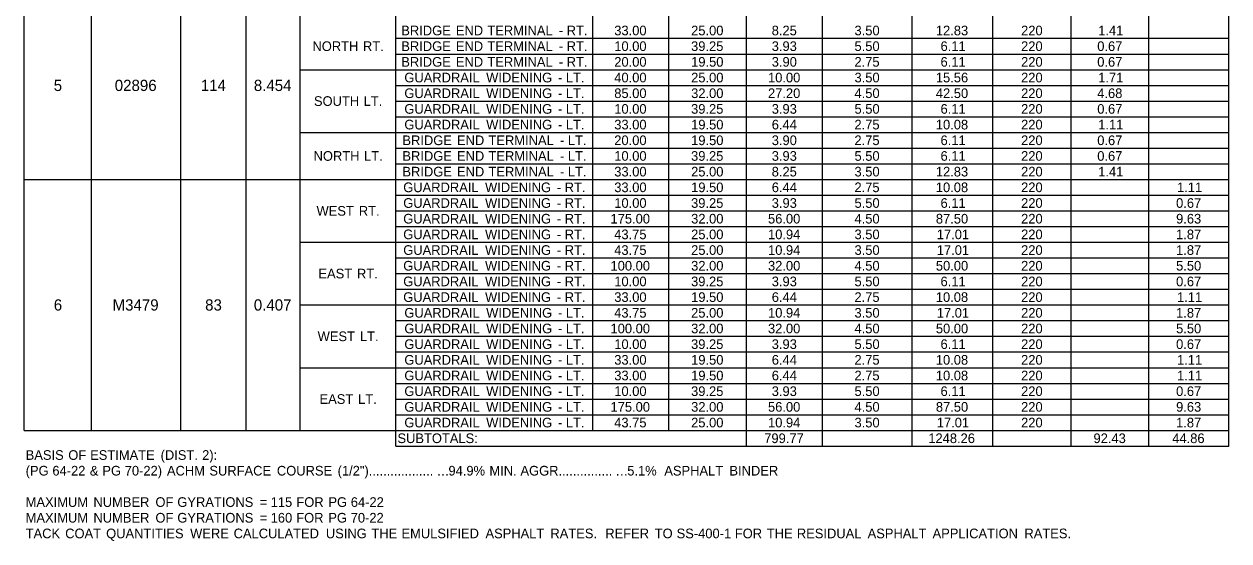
# Model space of a CAD drawing. Extents: x 542596 to 1930787, y -1948294 to 596640.
# Drawn here: x 552220 to 552968, y -1946907 to -1946586 of the extents above; entities that cross this region are included whole.
import ezdxf

# ---------------------------------------------------------------- set-up
doc = ezdxf.new("R2010")
doc.units = 0
doc.layers.add('Default', color=7, linetype='Continuous')

msp = doc.modelspace()

# ---------------------------------------------------------------- linework, layer by layer
at = {"layer": 'Default'}
for p, q in [((552219.67, -1946838.51), (552219.67, -1946129.69)), ((552261.6, -1946838.51), (552261.6, -1946129.69)), ((552317.17, -1946838.51), (552317.17, -1946129.69)), ((552357.64, -1946838.51), (552357.64, -1946129.69)), ((552391.27, -1946838.51), (552391.27, -1946129.69)), ((552450.75, -1946848.26), (552450.75, -1946129.69)), ((552573.11, -1946838.51), (552573.11, -1946129.69)), ((552620.4, -1946838.51), (552620.4, -1946129.69)), ((552715.95, -1946848.26), (552715.95, -1946129.69)), ((552968.47, -1946848.26), (552968.47, -1946129.69)), ((552668.66, -1946848.26), (552668.66, -1946155.04)), ((552771.52, -1946848.26), (552771.52, -1946155.04)), ((552821.74, -1946848.26), (552821.74, -1946155.04)), ((552870.49, -1946848.26), (552870.49, -1946155.04)), ((552918.75, -1946848.26), (552918.75, -1946155.04)), ((552821.74, -1946672.76), (552821.74, -1946565.51)), ((552450.75, -1946594.76), (552968.47, -1946594.76)), ((552620.4, -1946604.51), (552620.4, -1946594.76)), ((552668.66, -1946838.51), (552668.66, -1946594.76)), ((552771.52, -1946848.26), (552771.52, -1946594.76)), ((552450.75, -1946604.51), (552968.47, -1946604.51)), ((552391.27, -1946614.26), (552450.75, -1946614.26)), ((552391.27, -1946614.26), (552450.75, -1946614.26)), ((552450.75, -1946614.26), (552918.75, -1946614.26)), ((552573.11, -1946653.26), (552573.11, -1946614.26)), ((552620.4, -1946838.51), (552620.4, -1946614.26)), ((552821.74, -1946614.26), (552870.49, -1946614.26)), ((552870.49, -1946614.26), (552968.47, -1946614.26)), ((552450.75, -1946624.01), (552968.47, -1946624.01)), ((552450.75, -1946633.76), (552968.47, -1946633.76)), ((552450.75, -1946643.51), (552968.47, -1946643.51)), ((552391.27, -1946653.26), (552968.47, -1946653.26)), ((552391.27, -1946653.26), (552450.75, -1946653.26)), ((552450.75, -1946663.01), (552968.47, -1946663.01)), ((552450.75, -1946672.76), (552968.47, -1946672.76)), ((552219.67, -1946682.51), (552450.75, -1946682.51)), ((552219.67, -1946682.51), (552620.4, -1946682.51)), ((552450.75, -1946682.51), (552668.66, -1946682.51)), ((552573.11, -1946838.51), (552573.11, -1946682.51)), ((552620.4, -1946682.51), (552771.52, -1946682.51)), ((552715.95, -1946682.51), (552771.52, -1946682.51)), ((552771.52, -1946682.51), (552968.47, -1946682.51)), ((552821.74, -1946682.51), (552870.49, -1946682.51)), ((552821.74, -1946838.51), (552821.74, -1946682.51)), ((552870.49, -1946682.51), (552918.75, -1946682.51)), ((552918.75, -1946682.51), (552968.47, -1946682.51)), ((552450.75, -1946692.26), (552968.47, -1946692.26)), ((552450.75, -1946702.01), (552968.47, -1946702.01)), ((552450.75, -1946711.76), (552968.47, -1946711.76)), ((552391.27, -1946721.51), (552968.47, -1946721.51)), ((552391.27, -1946721.51), (552450.75, -1946721.51)), ((552450.75, -1946731.26), (552968.47, -1946731.26)), ((552450.75, -1946741.01), (552968.47, -1946741.01)), ((552450.75, -1946750.76), (552968.47, -1946750.76)), ((552391.27, -1946760.51), (552968.47, -1946760.51)), ((552391.27, -1946760.51), (552450.75, -1946760.51)), ((552450.75, -1946770.26), (552968.47, -1946770.26)), ((552450.75, -1946780.01), (552968.47, -1946780.01)), ((552450.75, -1946789.76), (552968.47, -1946789.76)), ((552391.27, -1946799.51), (552715.95, -1946799.51)), ((552391.27, -1946799.51), (552450.75, -1946799.51)), ((552668.66, -1946799.51), (552715.95, -1946799.51)), ((552715.95, -1946799.51), (552968.47, -1946799.51)), ((552450.75, -1946809.26), (552968.47, -1946809.26)), ((552450.75, -1946819.01), (552715.95, -1946819.01)), ((552668.66, -1946819.01), (552715.95, -1946819.01)), ((552715.95, -1946819.01), (552968.47, -1946819.01)), ((552450.75, -1946828.76), (552715.95, -1946828.76)), ((552668.66, -1946828.76), (552715.95, -1946828.76)), ((552715.95, -1946828.76), (552968.47, -1946828.76)), ((552219.67, -1946838.51), (552968.47, -1946838.51)), ((552391.27, -1946838.51), (552450.75, -1946838.51)), ((552450.75, -1946838.51), (552771.52, -1946838.51)), ((552450.75, -1946848.26), (552450.75, -1946838.51)), ((552771.52, -1946838.51), (552821.74, -1946838.51)), ((552821.74, -1946838.51), (552968.47, -1946838.51)), ((552870.49, -1946848.26), (552870.49, -1946838.51)), ((552450.75, -1946848.26), (552968.47, -1946848.26))]:
    msp.add_line(p, q, dxfattribs=at)

# ---------------------------------------------------------------- texts
for s, height, p in [('BRIDGE', 6, (552454.1, -1946592.89)), (' END', 6, (552485.8, -1946592.89)), (' TERMINAL', 6, (552505.38, -1946592.89)), (' RT.', 6, (552554.66, -1946592.89)), ('33.00', 6, (552586.47, -1946592.89)), ('25.00', 6, (552634.25, -1946592.89)), ('8.25', 6, (552684.32, -1946592.89)), ('3.50', 6, (552735.78, -1946592.89)), ('12.83', 6, (552786.34, -1946592.89)), ('220', 6, (552839.32, -1946592.89)), ('1.41', 6, (552887.24, -1946592.89)), (' -', 6, (552549.8, -1946592.89)), ('NORTH', 6, (552398.9, -1946602.64)), (' RT.', 6, (552428.03, -1946602.64)), ('BRIDGE', 6, (552454.1, -1946602.64)), (' END', 6, (552485.8, -1946602.64)), (' TERMINAL', 6, (552505.38, -1946602.64)), (' -', 6, (552549.8, -1946602.64)), (' RT.', 6, (552554.66, -1946602.64)), ('10.00', 6, (552586.47, -1946602.64)), ('39.25', 6, (552634.21, -1946602.64)), ('3.93', 6, (552684.34, -1946602.64)), ('5.50', 6, (552735.78, -1946602.64)), ('6.11', 6, (552789.25, -1946602.64)), ('220', 6, (552839.32, -1946602.64)), ('0.67', 6, (552886.65, -1946602.64)), ('BRIDGE', 6, (552454.1, -1946612.39)), (' END', 6, (552485.8, -1946612.39)), (' TERMINAL', 6, (552505.38, -1946612.39)), (' -', 6, (552549.8, -1946612.39)), (' RT.', 6, (552554.66, -1946612.39)), ('20.00', 6, (552586.47, -1946612.39)), ('19.50', 6, (552634.25, -1946612.39)), ('3.90', 6, (552684.35, -1946612.39)), ('2.75', 6, (552735.75, -1946612.39)), ('6.11', 6, (552789.25, -1946612.39)), ('220', 6, (552839.32, -1946612.39)), ('0.67', 6, (552886.65, -1946612.39)), ('GUARDRAIL', 6, (552456.02, -1946622.14)), (' WIDENING', 6, (552504.63, -1946622.14)), (' LT.', 6, (552554.14, -1946622.14)), ('40.00', 6, (552586.47, -1946622.14)), ('25.00', 6, (552634.25, -1946622.14)), ('10.00', 6, (552682.02, -1946622.14)), ('3.50', 6, (552735.78, -1946622.14)), ('15.56', 6, (552786.34, -1946622.14)), ('220', 6, (552839.32, -1946622.14)), ('1.71', 6, (552887.24, -1946622.14)), ('5', 7, (552238.11, -1946627.51)), ('02896', 7, (552276.02, -1946627.51)), ('114', 7, (552329.49, -1946627.51)), ('8.454', 7, (552362.46, -1946627.51)), (' -', 6, (552549.28, -1946622.14)), ('SOUTH', 6, (552399.82, -1946636.76)), (' LT.', 6, (552428.49, -1946636.76)), ('GUARDRAIL', 6, (552456.02, -1946631.89)), (' WIDENING', 6, (552504.63, -1946631.89)), (' -', 6, (552549.28, -1946631.89)), (' LT.', 6, (552554.14, -1946631.89)), ('85.00', 6, (552586.47, -1946631.89)), ('32.00', 6, (552634.25, -1946631.89)), ('27.20', 6, (552682.02, -1946631.89)), ('4.50', 6, (552735.78, -1946631.89)), ('42.50', 6, (552786.35, -1946631.89)), ('220', 6, (552839.32, -1946631.89)), ('4.68', 6, (552886.65, -1946631.89)), ('GUARDRAIL', 6, (552456.02, -1946641.64)), (' WIDENING', 6, (552504.63, -1946641.64)), (' -', 6, (552549.28, -1946641.64)), (' LT.', 6, (552554.14, -1946641.64)), ('10.00', 6, (552586.47, -1946641.64)), ('39.25', 6, (552634.21, -1946641.64)), ('3.93', 6, (552684.34, -1946641.64)), ('5.50', 6, (552735.78, -1946641.64)), ('6.11', 6, (552789.25, -1946641.64)), ('220', 6, (552839.32, -1946641.64)), ('0.67', 6, (552886.65, -1946641.64)), ('GUARDRAIL', 6, (552456.02, -1946651.39)), (' WIDENING', 6, (552504.63, -1946651.39)), (' LT.', 6, (552554.14, -1946651.39)), ('33.00', 6, (552586.47, -1946651.39)), ('19.50', 6, (552634.25, -1946651.39)), ('6.44', 6, (552684.36, -1946651.39)), ('2.75', 6, (552735.75, -1946651.39)), ('10.08', 6, (552786.33, -1946651.39)), ('220', 6, (552839.32, -1946651.39)), ('1.11', 6, (552887.24, -1946651.39)), ('BRIDGE', 6, (552454.8, -1946661.14)), (' END', 6, (552486.5, -1946661.14)), (' TERMINAL', 6, (552506.08, -1946661.14)), (' -', 6, (552549.28, -1946651.39)), (' LT.', 6, (552555.36, -1946661.14)), ('20.00', 6, (552586.47, -1946661.14)), ('19.50', 6, (552634.25, -1946661.14)), ('3.90', 6, (552684.35, -1946661.14)), ('2.75', 6, (552735.75, -1946661.14)), ('6.11', 6, (552789.25, -1946661.14)), ('220', 6, (552839.32, -1946661.14)), ('0.67', 6, (552886.65, -1946661.14)), (' -', 6, (552550.5, -1946661.14)), ('NORTH', 6, (552399.59, -1946670.89)), (' LT.', 6, (552428.72, -1946670.89)), ('BRIDGE', 6, (552454.8, -1946670.89)), (' END', 6, (552486.5, -1946670.89)), (' TERMINAL', 6, (552506.08, -1946670.89)), (' -', 6, (552550.5, -1946670.89)), (' LT.', 6, (552555.36, -1946670.89)), ('10.00', 6, (552586.47, -1946670.89)), ('39.25', 6, (552634.21, -1946670.89)), ('3.93', 6, (552684.34, -1946670.89)), ('5.50', 6, (552735.78, -1946670.89)), ('6.11', 6, (552789.25, -1946670.89)), ('220', 6, (552839.32, -1946670.89)), ('0.67', 6, (552886.65, -1946670.89)), ('BRIDGE', 6, (552454.8, -1946680.64)), (' END', 6, (552486.5, -1946680.64)), (' TERMINAL', 6, (552506.08, -1946680.64)), (' LT.', 6, (552555.36, -1946680.64)), ('33.00', 6, (552586.47, -1946680.64)), ('25.00', 6, (552634.25, -1946680.64)), ('8.25', 6, (552684.32, -1946680.64)), ('3.50', 6, (552735.78, -1946680.64)), ('12.83', 6, (552786.34, -1946680.64)), ('220', 6, (552839.32, -1946680.64)), ('1.41', 6, (552887.24, -1946680.64)), ('GUARDRAIL', 6, (552455.32, -1946690.39)), (' WIDENING', 6, (552503.94, -1946690.39)), (' -', 6, (552550.5, -1946680.64)), (' RT.', 6, (552553.44, -1946690.39)), ('33.00', 6, (552586.47, -1946690.39)), ('19.50', 6, (552634.25, -1946690.39)), ('6.44', 6, (552684.36, -1946690.39)), ('2.75', 6, (552735.75, -1946690.39)), ('10.08', 6, (552786.33, -1946690.39)), ('220', 6, (552839.32, -1946690.39)), ('1.11', 6, (552936.23, -1946690.39)), (' -', 6, (552548.58, -1946690.39)), ('WEST', 6, (552401.44, -1946705.01)), (' RT.', 6, (552425.49, -1946705.01)), ('GUARDRAIL', 6, (552455.32, -1946700.14)), (' WIDENING', 6, (552503.94, -1946700.14)), (' -', 6, (552548.58, -1946700.14)), (' RT.', 6, (552553.44, -1946700.14)), ('10.00', 6, (552586.47, -1946700.14)), ('39.25', 6, (552634.21, -1946700.14)), ('3.93', 6, (552684.34, -1946700.14)), ('5.50', 6, (552735.78, -1946700.14)), ('6.11', 6, (552789.25, -1946700.14)), ('220', 6, (552839.32, -1946700.14)), ('0.67', 6, (552935.65, -1946700.14)), ('GUARDRAIL', 6, (552455.32, -1946709.89)), (' WIDENING', 6, (552503.94, -1946709.89)), (' -', 6, (552548.58, -1946709.89)), (' RT.', 6, (552553.44, -1946709.89)), ('175.00', 6, (552584.14, -1946709.89)), ('32.00', 6, (552634.25, -1946709.89)), ('56.00', 6, (552682.02, -1946709.89)), ('4.50', 6, (552735.78, -1946709.89)), ('87.50', 6, (552786.35, -1946709.89)), ('220', 6, (552839.32, -1946709.89)), ('9.63', 6, (552935.65, -1946709.89)), ('GUARDRAIL', 6, (552455.32, -1946719.64)), (' WIDENING', 6, (552503.94, -1946719.64)), (' RT.', 6, (552553.44, -1946719.64)), ('43.75', 6, (552586.44, -1946719.64)), ('25.00', 6, (552634.25, -1946719.64)), ('10.94', 6, (552682.03, -1946719.64)), ('3.50', 6, (552735.78, -1946719.64)), ('17.01', 6, (552786.92, -1946719.64)), ('220', 6, (552839.32, -1946719.64)), ('1.87', 6, (552935.65, -1946719.64)), (' -', 6, (552548.58, -1946719.64)), ('GUARDRAIL', 6, (552455.32, -1946729.39)), (' WIDENING', 6, (552503.94, -1946729.39)), (' -', 6, (552548.58, -1946729.39)), (' RT.', 6, (552553.44, -1946729.39)), ('43.75', 6, (552586.44, -1946729.39)), ('25.00', 6, (552634.25, -1946729.39)), ('10.94', 6, (552682.03, -1946729.39)), ('3.50', 6, (552735.78, -1946729.39)), ('17.01', 6, (552786.92, -1946729.39)), ('220', 6, (552839.32, -1946729.39)), ('1.87', 6, (552935.65, -1946729.39)), ('GUARDRAIL', 6, (552455.32, -1946739.14)), (' WIDENING', 6, (552503.94, -1946739.14)), (' -', 6, (552548.58, -1946739.14)), (' RT.', 6, (552553.44, -1946739.14)), ('100.00', 6, (552584.14, -1946739.14)), ('32.00', 6, (552634.25, -1946739.14)), ('32.00', 6, (552682.02, -1946739.14)), ('4.50', 6, (552735.78, -1946739.14)), ('50.00', 6, (552786.35, -1946739.14)), ('220', 6, (552839.32, -1946739.14)), ('5.50', 6, (552935.66, -1946739.14)), ('EAST', 6, (552402.6, -1946744.01)), (' RT.', 6, (552424.33, -1946744.01)), ('GUARDRAIL', 6, (552455.32, -1946748.89)), (' WIDENING', 6, (552503.94, -1946748.89)), (' RT.', 6, (552553.44, -1946748.89)), ('10.00', 6, (552586.47, -1946748.89)), ('39.25', 6, (552634.21, -1946748.89)), ('3.93', 6, (552684.34, -1946748.89)), ('5.50', 6, (552735.78, -1946748.89)), ('6.11', 6, (552789.25, -1946748.89)), ('220', 6, (552839.32, -1946748.89)), ('0.67', 6, (552935.65, -1946748.89)), ('GUARDRAIL', 6, (552455.32, -1946758.64)), (' WIDENING', 6, (552503.94, -1946758.64)), (' -', 6, (552548.58, -1946748.89)), (' RT.', 6, (552553.44, -1946758.64)), ('33.00', 6, (552586.47, -1946758.64)), ('19.50', 6, (552634.25, -1946758.64)), ('6.44', 6, (552684.36, -1946758.64)), ('2.75', 6, (552735.75, -1946758.64)), ('10.08', 6, (552786.33, -1946758.64)), ('220', 6, (552839.32, -1946758.64)), ('1.11', 6, (552936.23, -1946758.64)), ('6', 7, (552238.14, -1946764.01)), ('M3479', 7, (552274.66, -1946764.01)), ('83', 7, (552332.19, -1946764.01)), ('0.407', 7, (552362.45, -1946764.01)), (' -', 6, (552548.58, -1946758.64)), ('GUARDRAIL', 6, (552456.02, -1946768.39)), (' WIDENING', 6, (552504.63, -1946768.39)), (' -', 6, (552549.28, -1946768.39)), (' LT.', 6, (552554.14, -1946768.39)), ('43.75', 6, (552586.44, -1946768.39)), ('25.00', 6, (552634.25, -1946768.39)), ('10.94', 6, (552682.03, -1946768.39)), ('3.50', 6, (552735.78, -1946768.39)), ('17.01', 6, (552786.92, -1946768.39)), ('220', 6, (552839.32, -1946768.39)), ('1.87', 6, (552935.65, -1946768.39)), ('GUARDRAIL', 6, (552456.02, -1946778.14)), (' WIDENING', 6, (552504.63, -1946778.14)), (' LT.', 6, (552554.14, -1946778.14)), ('100.00', 6, (552584.14, -1946778.14)), ('32.00', 6, (552634.25, -1946778.14)), ('32.00', 6, (552682.02, -1946778.14)), ('4.50', 6, (552735.78, -1946778.14)), ('50.00', 6, (552786.35, -1946778.14)), ('220', 6, (552839.32, -1946778.14)), ('5.50', 6, (552935.66, -1946778.14)), ('WEST', 6, (552402.13, -1946783.01)), (' LT.', 6, (552426.18, -1946783.01)), ('GUARDRAIL', 6, (552456.02, -1946787.89)), (' WIDENING', 6, (552504.63, -1946787.89)), (' -', 6, (552549.28, -1946778.14)), (' LT.', 6, (552554.14, -1946787.89)), ('10.00', 6, (552586.47, -1946787.89)), ('39.25', 6, (552634.21, -1946787.89)), ('3.93', 6, (552684.34, -1946787.89)), ('5.50', 6, (552735.78, -1946787.89)), ('6.11', 6, (552789.25, -1946787.89)), ('220', 6, (552839.32, -1946787.89)), ('0.67', 6, (552935.65, -1946787.89)), (' -', 6, (552549.28, -1946787.89)), ('GUARDRAIL', 6, (552456.02, -1946797.64)), (' WIDENING', 6, (552504.63, -1946797.64)), (' -', 6, (552549.28, -1946797.64)), (' LT.', 6, (552554.14, -1946797.64)), ('33.00', 6, (552586.47, -1946797.64)), ('19.50', 6, (552634.25, -1946797.64)), ('6.44', 6, (552684.36, -1946797.64)), ('2.75', 6, (552735.75, -1946797.64)), ('10.08', 6, (552786.33, -1946797.64)), ('220', 6, (552839.32, -1946797.64)), ('1.11', 6, (552936.23, -1946797.64)), ('GUARDRAIL', 6, (552456.02, -1946807.39)), (' WIDENING', 6, (552504.63, -1946807.39)), (' -', 6, (552549.28, -1946807.39)), (' LT.', 6, (552554.14, -1946807.39)), ('33.00', 6, (552586.47, -1946807.39)), ('19.50', 6, (552634.25, -1946807.39)), ('6.44', 6, (552684.36, -1946807.39)), ('2.75', 6, (552735.75, -1946807.39)), ('10.08', 6, (552786.33, -1946807.39)), ('220', 6, (552839.32, -1946807.39)), ('1.11', 6, (552936.23, -1946807.39)), ('GUARDRAIL', 6, (552456.02, -1946817.14)), (' WIDENING', 6, (552504.63, -1946817.14)), (' LT.', 6, (552554.14, -1946817.14)), ('10.00', 6, (552586.47, -1946817.14)), ('39.25', 6, (552634.21, -1946817.14)), ('3.93', 6, (552684.34, -1946817.14)), ('5.50', 6, (552735.78, -1946817.14)), ('6.11', 6, (552789.25, -1946817.14)), ('220', 6, (552839.32, -1946817.14)), ('0.67', 6, (552935.65, -1946817.14)), ('EAST', 6, (552403.29, -1946822.01)), (' LT.', 6, (552425.03, -1946822.01)), (' -', 6, (552549.28, -1946817.14)), ('GUARDRAIL', 6, (552456.02, -1946826.89)), (' WIDENING', 6, (552504.63, -1946826.89)), (' -', 6, (552549.28, -1946826.89)), (' LT.', 6, (552554.14, -1946826.89)), ('175.00', 6, (552584.14, -1946826.89)), ('32.00', 6, (552634.25, -1946826.89)), ('56.00', 6, (552682.02, -1946826.89)), ('4.50', 6, (552735.78, -1946826.89)), ('87.50', 6, (552786.35, -1946826.89)), ('220', 6, (552839.32, -1946826.89)), ('9.63', 6, (552935.65, -1946826.89)), ('GUARDRAIL', 6, (552456.02, -1946836.64)), (' WIDENING', 6, (552504.63, -1946836.64)), (' -', 6, (552549.28, -1946836.64)), (' LT.', 6, (552554.14, -1946836.64)), ('43.75', 6, (552586.44, -1946836.64)), ('25.00', 6, (552634.25, -1946836.64)), ('10.94', 6, (552682.03, -1946836.64)), ('3.50', 6, (552735.78, -1946836.64)), ('17.01', 6, (552786.92, -1946836.64)), ('220', 6, (552839.32, -1946836.64)), ('1.87', 6, (552935.65, -1946836.64)), ('SUBTOTALS:', 6, (552451.72, -1946846.39)), ('799.77', 6, (552679.68, -1946846.39)), ('1248.26', 6, (552781.64, -1946846.39)), ('92.43', 6, (552884.32, -1946846.39)), ('44.86', 6, (552933.28, -1946846.39)), ('BASIS', 6, (552220.65, -1946856.81)), (' OF', 6, (552244.91, -1946856.81)), (' ESTIMATE', 6, (552258.5, -1946856.81)), (' (DIST.', 6, (552302.3, -1946856.81)), (' 2):', 6, (552328.11, -1946856.81)), ('(PG', 6, (552220.65, -1946866.56)), (' 64-22', 6, (552235.03, -1946866.56)), (' &', 6, (552258.34, -1946866.56)), (' PG', 6, (552266.07, -1946866.56)), (' 70-22)', 6, (552279.99, -1946866.56)), (' ACHM', 6, (552306.23, -1946866.56)), (' SURFACE', 6, (552332.61, -1946866.56)), (' COURSE', 6, (552374.56, -1946866.56)), (' (1/2")..................', 6, (552412.31, -1946866.56)), ('94.9%', 6, (552483.41, -1946866.56)), (' MIN.', 6, (552506.65, -1946866.56)), (' AGGR...............', 6, (552525.94, -1946866.56)), ('5.1%', 6, (552594.54, -1946866.56)), ('  ASPHALT', 6, (552613.12, -1946866.56)), (' BINDER', 6, (552655.82, -1946866.56)), ('…', 6, (552476.01, -1946866.56)), ('…', 6, (552587.14, -1946866.56)), (' OF', 6, (552299.08, -1946886.06)), (' GYRATIONS', 6, (552312.67, -1946886.06)), (' FOR', 6, (552386.67, -1946886.06)), (' PG', 6, (552406.58, -1946886.06)), (' 64-22', 6, (552420.5, -1946886.06)), ('MAXIMUM', 6, (552220.65, -1946886.06)), (' NUMBER', 6, (552260.54, -1946886.06)), (' =', 6, (552363.94, -1946886.06)), (' 115', 6, (552370.7, -1946886.06)), ('MAXIMUM', 6, (552220.65, -1946895.81)), (' NUMBER', 6, (552260.54, -1946895.81)), (' OF', 6, (552299.08, -1946895.81)), (' GYRATIONS', 6, (552312.67, -1946895.81)), (' =', 6, (552363.94, -1946895.81)), (' 160', 6, (552370.7, -1946895.81)), (' FOR', 6, (552386.6, -1946895.81)), (' PG', 6, (552406.51, -1946895.81)), (' 70-22', 6, (552420.43, -1946895.81)), ('TACK', 6, (552220.65, -1946905.56)), (' COAT', 6, (552242.99, -1946905.56)), (' QUANTITIES', 6, (552268.44, -1946905.56)), (' WERE', 6, (552320.64, -1946905.56)), (' CALCULATED', 6, (552347.67, -1946905.56)), (' USING', 6, (552404.99, -1946905.56)), (' THE', 6, (552433.35, -1946905.56)), (' EMULSIFIED', 6, (552452, -1946905.56)), (' ASPHALT', 6, (552504.19, -1946905.56)), (' RATES.', 6, (552544.55, -1946905.56)), ('  REFER', 6, (552576.43, -1946905.56)), (' TO', 6, (552609.39, -1946905.56)), (' SS-400-1', 6, (552622.99, -1946905.56)), (' FOR', 6, (552659.18, -1946905.56)), (' THE', 6, (552679.09, -1946905.56)), (' RESIDUAL', 6, (552697.74, -1946905.56)), (' ASPHALT', 6, (552741.7, -1946905.56)), (' APPLICATION', 6, (552782.07, -1946905.56)), (' RATES.', 6, (552839.15, -1946905.56))]:
    msp.add_text(s, height=height, dxfattribs=at).set_placement(p)

doc.saveas('drawing.dxf')
